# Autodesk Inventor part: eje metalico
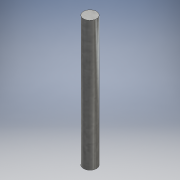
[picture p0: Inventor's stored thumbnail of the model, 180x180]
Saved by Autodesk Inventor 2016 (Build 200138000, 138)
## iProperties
Created: 2016-06
Part Number: eje metalico
Material: Genérico
Document SubType Name: Modeling
Designer: adm
Density: 1 g/cm^3
Appearance: Valor por defecto
Author: adm
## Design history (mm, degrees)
sketch "Boceto1"
  geometry: C1 r 5 at (0, 0); 1 further point
  constraints: 1 centre point, 1 coincident
  dimensions: "d0" = 10 diameter of C1
extrude "Extrusión1" new body sketch "Boceto1" distance "d1" = 100; taper "d2" = 0 deg
node "Sólido1"
